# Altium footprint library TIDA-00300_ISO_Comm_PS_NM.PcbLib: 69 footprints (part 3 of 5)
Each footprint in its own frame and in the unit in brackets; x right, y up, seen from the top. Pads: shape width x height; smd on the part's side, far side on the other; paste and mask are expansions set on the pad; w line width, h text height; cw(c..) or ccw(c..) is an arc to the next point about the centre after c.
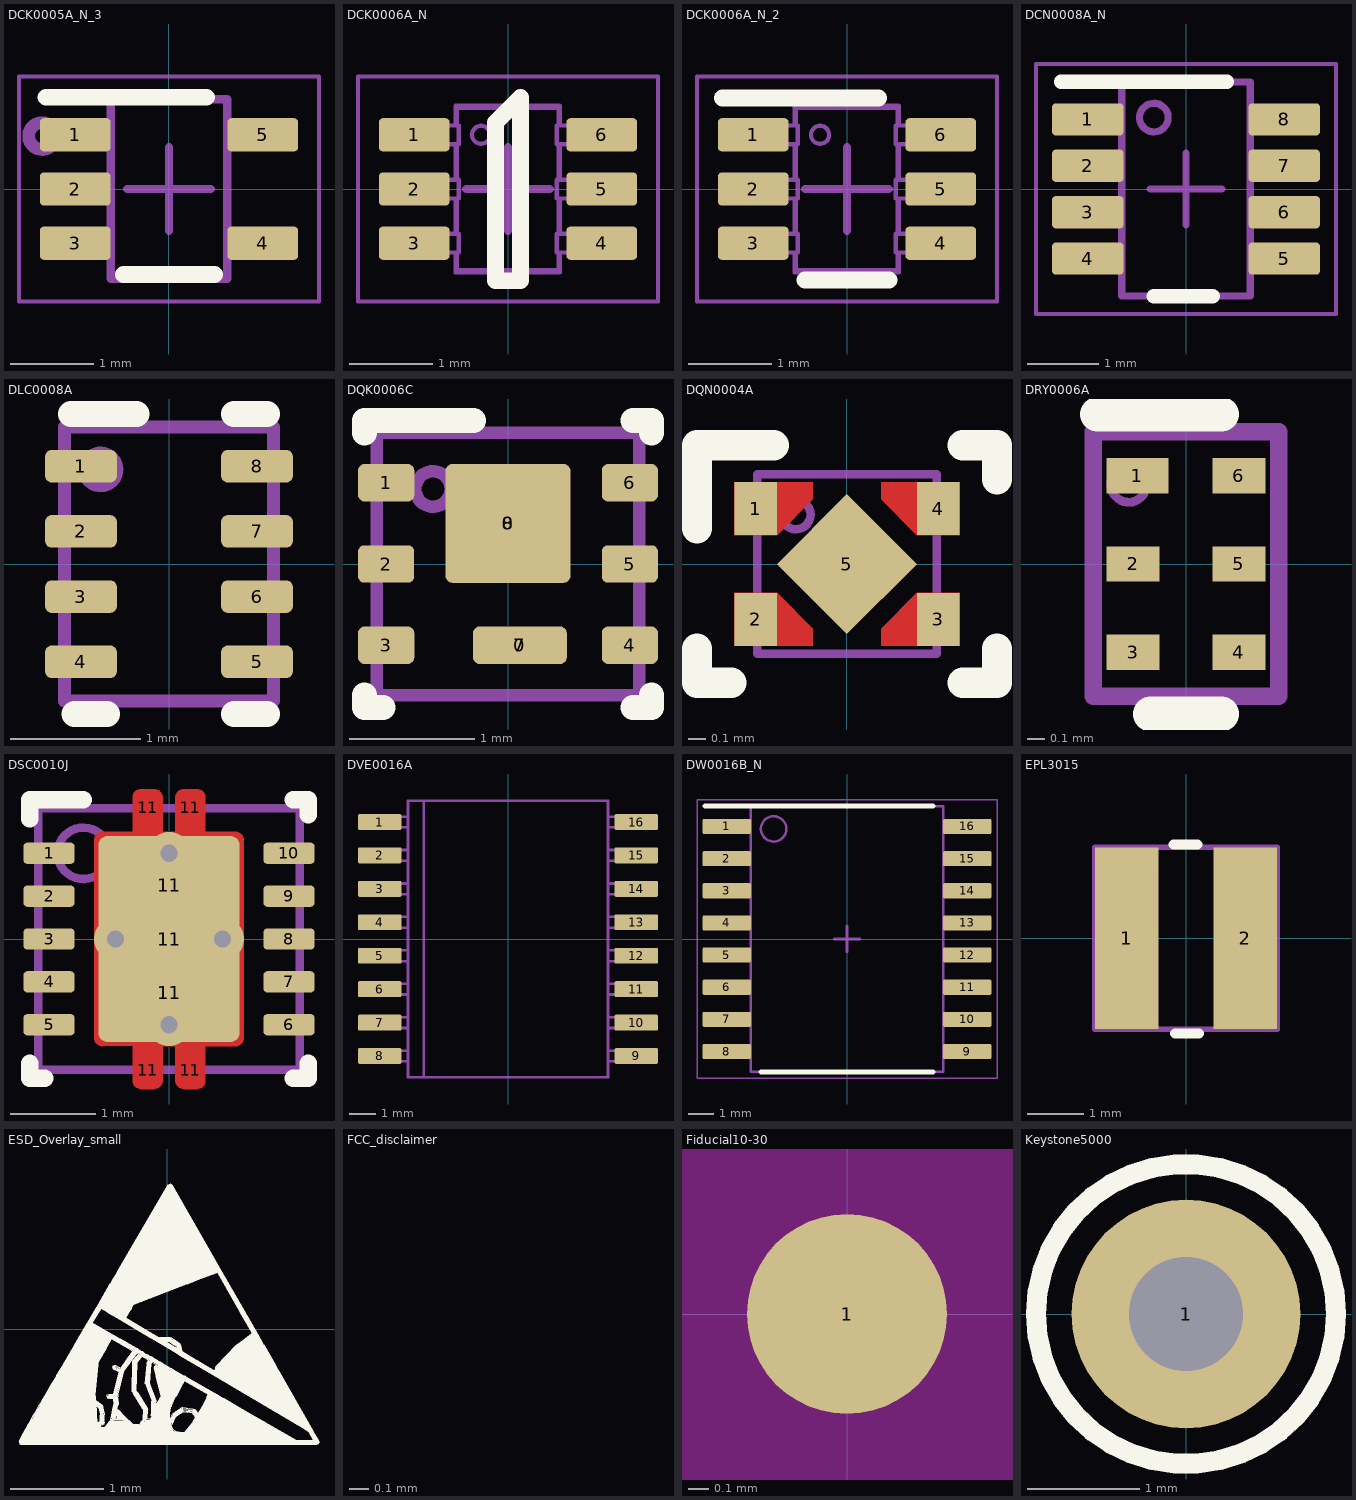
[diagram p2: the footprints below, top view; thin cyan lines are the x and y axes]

## DCK0005A_N_3 [mm]
pads (5):
  rrect25% 0.85x0.4 smd: 1(-1.125,0.65) 2(-1.125,0) 3(-1.125,-0.65) 4(1.125,-0.65) 5(1.125,0.65)
Top Overlay:
  lines w0.2: -1.475,1.1 0.45,1.1 ; -0.55,-1.025 0.55,-1.025
Mechanical 5:
  circle w0.152: c-1.524,0.635 r0.16
  lines w0.1: -0.7,-1.075 0.7,-1.075 0.7,1.075 -0.7,1.075 -0.7,-1.075
  lines w0.127: -0.865,0.762 -0.853,0.762 ; -0.711,-0.763 -0.853,-0.763 -0.865,-0.763 -0.959,-0.763 -1.143,-0.763 -1.143,-0.538 -0.959,-0.538 -0.865,-0.538 -0.853,-0.538 -0.711,-0.538 ; -0.711,-0.113 -0.853,-0.113 -0.865,-0.113 -0.959,-0.113 -1.143,-0.113 -1.143,0.112 -0.959,0.112 -0.865,0.112 -0.853,0.112 -0.711,0.112 ; -0.711,0.537 -0.853,0.537 -0.865,0.537 -0.959,0.537 -1.143,0.537 -1.143,0.762 -0.959,0.762 -0.711,0.762 ; 0.711,-0.763 0.847,-0.763 0.859,-0.763 0.953,-0.763 1.137,-0.763 1.137,-0.538 0.953,-0.538 0.859,-0.538 0.847,-0.538 0.711,-0.538 ; 0.711,0.537 0.847,0.537 0.859,0.537 0.953,0.537 1.137,0.537 1.137,0.762 0.953,0.762 0.859,0.762 0.847,0.762 0.711,0.762
  text ".Designator" at -0.254,0.537 h0.51
Mechanical 15:
  lines w0.05: -1.8,-1.35 1.8,-1.35 1.8,1.35 -1.8,1.35 -1.8,-1.35
  lines w0.1: -0.5,0 0.5,0 ; 0,-0.5 0,0.5
3D body "DCK0005A.stp": height 0.95, standoff 0, extent -1.14,-1 1.14,1

## DCK0006A_N [mm] "SOT23, 6-Leads, Body 2x1.3mm, Pitch 0.65mm, Lead Span 2.1mm, IPC Medium Density"
height 1.1
pads (6):
  rrect25% 0.85x0.4 smd: 1(-1.125,0.65) 2(-1.125,0) 3(-1.125,-0.65) 4(1.125,-0.65) 5(1.125,0) 6(1.125,0.65)
Top Overlay:
  lines w0.2: -0.15,-1.1 0.15,-1.1 0.15,1.1 -0.15,0.8 -0.15,-1.1
Mechanical 5:
  lines w0.05: -0.613,-0.763 -0.613,-0.976 0.607,-0.976 0.607,-0.763 ; -0.613,-0.538 -0.613,-0.113 ; -0.613,0.112 -0.613,0.537 ; -0.613,0.762 -0.613,0.974 0.607,0.974 0.607,0.762 ; 0.607,-0.538 0.607,-0.113 ; 0.607,0.112 0.607,0.537 ; -0.628,-0.763 -0.591,-0.763 -0.591,-0.538 -0.628,-0.538 ; -0.628,-0.763 -0.853,-0.763 -0.865,-0.763 -0.959,-0.763 -1.143,-0.763 -1.143,-0.538 -0.959,-0.538 -0.865,-0.538 -0.853,-0.538 -0.628,-0.538 ; -0.628,-0.763 -0.628,-1.001 0.622,-1.001 0.622,-0.763 ; -0.628,-0.538 -0.628,-0.113 ; -0.628,-0.113 -0.591,-0.113 -0.591,0.112 -0.628,0.112 ; -0.628,-0.113 -0.853,-0.113 -0.865,-0.113 -0.959,-0.113 -1.143,-0.113 -1.143,0.112 -0.959,0.112 -0.865,0.112 -0.853,0.112 -0.628,0.112 ; -0.628,0.112 -0.628,0.537 ; -0.628,0.537 -0.591,0.537 -0.591,0.762 -0.628,0.762 ; -0.628,0.537 -0.853,0.537 -0.865,0.537 -0.959,0.537 -1.143,0.537 -1.143,0.762 -0.959,0.762 -0.865,0.762 -0.853,0.762 -0.628,0.762 ; -0.628,0.762 -0.628,0.999 0.622,0.999 0.622,0.762 ; 0.622,-0.763 0.585,-0.763 0.585,-0.538 0.622,-0.538 ; 0.622,-0.763 0.847,-0.763 0.859,-0.763 0.953,-0.763 1.137,-0.763 1.137,-0.538 0.953,-0.538 0.859,-0.538 0.847,-0.538 0.622,-0.538 ; 0.622,-0.538 0.622,-0.113 ; 0.622,-0.113 0.847,-0.113 0.859,-0.113 0.953,-0.113 1.137,-0.113 1.137,0.112 0.953,0.112 0.859,0.112 0.847,0.112 0.622,0.112 ; 0.622,-0.113 0.585,-0.113 0.585,0.112 0.622,0.112 ; 0.622,0.112 0.622,0.537 ; 0.622,0.537 0.585,0.537 0.585,0.762 0.622,0.762 ; 0.622,0.537 0.847,0.537 0.859,0.537 0.953,0.537 1.137,0.537 1.137,0.762 0.953,0.762 0.859,0.762 0.847,0.762 0.622,0.762 ; -0.432,0.65 ccw(c-0.323,0.65) -0.215,0.65 ccw(c-0.323,0.65) -0.432,0.65
  text ".Designator" at 0.279,-0.635 h0.51
Mechanical 15:
  lines w0.05: -1.8,-1.35 1.8,-1.35 1.8,1.35 -1.8,1.35 -1.8,-1.35
  lines w0.1: -0.5,0 0.5,0 ; 0,-0.5 0,0.5
3D body "DCK0006A.stp": height 0.95, standoff 0, extent -1.14,-1 1.14,1

## DCK0006A_N_2 [mm]
pads (6):
  rrect25% 0.85x0.4 smd: 1(-1.125,0.65) 2(-1.125,0) 3(-1.125,-0.65) 4(1.125,-0.65) 5(1.125,0) 6(1.125,0.65)
Top Overlay:
  lines w0.2: -1.499,1.092 0.381,1.092 ; -0.508,-1.092 0.508,-1.092
Mechanical 5:
  lines w0.05: -0.613,-0.763 -0.613,-0.976 0.607,-0.976 0.607,-0.763 ; -0.613,-0.538 -0.613,-0.113 ; -0.613,0.112 -0.613,0.537 ; -0.613,0.762 -0.613,0.974 0.607,0.974 0.607,0.762 ; 0.607,-0.538 0.607,-0.113 ; 0.607,0.112 0.607,0.537 ; -0.628,-0.763 -0.591,-0.763 -0.591,-0.538 -0.628,-0.538 ; -0.628,-0.763 -0.853,-0.763 -0.865,-0.763 -0.959,-0.763 -1.143,-0.763 -1.143,-0.538 -0.959,-0.538 -0.865,-0.538 -0.853,-0.538 -0.628,-0.538 ; -0.628,-0.763 -0.628,-1.001 0.622,-1.001 0.622,-0.763 ; -0.628,-0.538 -0.628,-0.113 ; -0.628,-0.113 -0.591,-0.113 -0.591,0.112 -0.628,0.112 ; -0.628,-0.113 -0.853,-0.113 -0.865,-0.113 -0.959,-0.113 -1.143,-0.113 -1.143,0.112 -0.959,0.112 -0.865,0.112 -0.853,0.112 -0.628,0.112 ; -0.628,0.112 -0.628,0.537 ; -0.628,0.537 -0.591,0.537 -0.591,0.762 -0.628,0.762 ; -0.628,0.537 -0.853,0.537 -0.865,0.537 -0.959,0.537 -1.143,0.537 -1.143,0.762 -0.959,0.762 -0.865,0.762 -0.853,0.762 -0.628,0.762 ; -0.628,0.762 -0.628,0.999 0.622,0.999 0.622,0.762 ; 0.622,-0.763 0.585,-0.763 0.585,-0.538 0.622,-0.538 ; 0.622,-0.763 0.847,-0.763 0.859,-0.763 0.953,-0.763 1.137,-0.763 1.137,-0.538 0.953,-0.538 0.859,-0.538 0.847,-0.538 0.622,-0.538 ; 0.622,-0.538 0.622,-0.113 ; 0.622,-0.113 0.847,-0.113 0.859,-0.113 0.953,-0.113 1.137,-0.113 1.137,0.112 0.953,0.112 0.859,0.112 0.847,0.112 0.622,0.112 ; 0.622,-0.113 0.585,-0.113 0.585,0.112 0.622,0.112 ; 0.622,0.112 0.622,0.537 ; 0.622,0.537 0.585,0.537 0.585,0.762 0.622,0.762 ; 0.622,0.537 0.847,0.537 0.859,0.537 0.953,0.537 1.137,0.537 1.137,0.762 0.953,0.762 0.859,0.762 0.847,0.762 0.622,0.762 ; -0.432,0.65 ccw(c-0.323,0.65) -0.215,0.65 ccw(c-0.323,0.65) -0.432,0.65
  text ".Designator" at -0.152,0.381 h0.51
Mechanical 15:
  lines w0.05: -1.8,-1.35 1.8,-1.35 1.8,1.35 -1.8,1.35 -1.8,-1.35
  lines w0.1: -0.5,0 0.5,0 ; 0,-0.5 0,0.5
3D body "DCK0006A.stp": height 0.95, standoff 0, extent -1.14,-1 1.14,1

## DCN0008A_N [mm] "SOP, 8-Leads, Body 2.9x1.6mm, Pitch 0.65mm, IPC Medium Density"
height 1.45
pads (8):
  rrect22% 1x0.45 smd: 1(-1.375,0.975) 2(-1.375,0.325) 3(-1.375,-0.325) 4(-1.375,-0.975) 5(1.375,-0.975) 6(1.375,-0.325) 7(1.375,0.325) 8(1.375,0.975)
Top Overlay:
  lines w0.2: -1.75,1.5 0.575,1.5 ; -0.45,-1.5 0.375,-1.5
Mechanical 5:
  circle w0.1: c-0.45,1 r0.2
  lines w0.1: -0.9,-1.5 -0.9,1.5 0.9,1.5 0.9,-1.5 -0.9,-1.5
  text ".Designator" at -0.66,-0.503 h0.51
Mechanical 15:
  lines w0.05: -2.1,-1.75 2.1,-1.75 2.1,1.75 -2.1,1.75 -2.1,-1.75
  lines w0.1: -0.5,0 0.5,0 ; 0,-0.5 0,0.5
3D body "DCN0008A.stp": height 1.45, standoff 0, extent -1.405,-1.45 1.405,1.45

## DLC0008A [mm] "VSON-HR-8"
height 1
pads (8):
  rrect40% 0.55x0.25 smd: 1(-0.675,0.75) 2(-0.675,0.25) 3(-0.675,-0.25) 4(-0.675,-0.75) 5(0.675,-0.75) 6(0.675,-0.25) 7(0.675,0.25) 8(0.675,0.75)
Top Overlay:
  lines w0.2: -0.75,1.15 -0.25,1.15 ; -0.725,-1.15 -0.475,-1.15 ; 0.5,-1.15 0.75,-1.15 ; 0.5,1.15 0.75,1.15
Mechanical 5:
  circle w0.1: c-0.525,0.725 r0.125
  lines w0.1: -0.8,-1.05 -0.8,1.05 0.8,1.05 0.8,-1.05 -0.8,-1.05
  text ".Designator" at -0.265,2.579 h0.51
3D body: height 1, standoff 0, extent -0.799,-1.049 0.799,1.049
3D body: height 1.02, standoff 0.5, extent -0.549,0.601 -0.301,0.849

## DQK0006C [mm] "WSON"
height 0.8
pads (10):
  rrect50% 0.9x0.86 on Top Paste: 0(0,0.325)
  rrect50% 0.7x0.29 on Top Paste: 0(0.095,-0.65)
  rrect33% 0.45x0.3 smd: 1(-0.975,0.65) 2(-0.975,0) 3(-0.975,-0.65) 4(0.975,-0.65) 5(0.975,0) 6(0.975,0.65)
  rrect33% 0.75x0.3 smd paste-0.15: 7(0.095,-0.65)
  rrect11% 1x0.95 smd paste-0.5: 8(0,0.325)
Top Overlay:
  lines w0.2: -1.15,-1.05 -1.15,-1.15 -1,-1.15 ; -1.15,1.05 -1.15,1.15 -0.275,1.15 ; 1,-1.15 1.15,-1.15 1.15,-1.05 ; 1,1.15 1.15,1.15 1.15,1.05
Mechanical 5:
  circle w0.1: c-0.6,0.6 r0.141
  lines w0.1: -1.05,-1.05 -1.05,1.05 1.05,1.05 1.05,-1.05 -1.05,-1.05
  text ".Designator" at 0.193,0.163 h0.51
3D body "DQK0006C.stp": height 0.82, standoff 0, extent -1,-1 1,1

## DQN0004A [mm] "SON, 0.65mm pitch"
height 0.4
pads (5):
  rect 0.25x0.31 smd paste-1 mask-0.31: 1(-0.535,0.325) 2(-0.535,-0.325) 3(0.535,-0.325) 4(0.535,0.325)
  rect 0.58x0.58 smd rot 45 paste-0.065 mask-0.05: 5(0,0)
Top Layer:
  region: -0.66,0.48 -0.2,0.48 -0.2,0.379 -0.409,0.17 -0.66,0.17
  region: 0.66,0.48 0.2,0.48 0.2,0.379 0.409,0.17 0.66,0.17
  region: 0.66,-0.48 0.2,-0.48 0.2,-0.379 0.409,-0.17 0.66,-0.17
  region: -0.66,-0.48 -0.2,-0.48 -0.2,-0.379 -0.409,-0.17 -0.66,-0.17
Top Overlay:
  lines w0.178: -0.88,-0.496 -0.88,-0.696 -0.68,-0.696 ; -0.88,0.21 -0.88,0.696 -0.43,0.696 ; 0.68,-0.696 0.88,-0.696 0.88,-0.496 ; 0.68,0.696 0.88,0.696 0.88,0.496
Top Paste:
  region: -0.65,-0.43 -0.25,-0.43 -0.25,-0.4 -0.43,-0.22 -0.65,-0.22
  region: 0.65,-0.43 0.25,-0.43 0.25,-0.4 0.43,-0.22 0.65,-0.22
  region: 0.65,0.43 0.25,0.43 0.25,0.4 0.43,0.22 0.65,0.22
  region: -0.65,0.43 -0.25,0.43 -0.25,0.4 -0.43,0.22 -0.65,0.22
Mechanical 5:
  circle w0.05: c-0.3,0.29 r0.086
  lines w0.05: -0.525,-0.525 -0.525,0.525 0.525,0.525 0.525,-0.525 -0.525,-0.525
  text ".Designator" at 0.616,-0.781 h0.51
3D body: height 0.4, standoff 0, extent -0.525,-0.525 0.525,0.525
3D body: height 0.42, standoff 0.2, extent -0.386,0.204 -0.214,0.376

## DRY0006A [mm] "PSON, 6-Leads, Body 1x1.45mm, Pitch 0.5mm, TI Recommended"
height 0.6
pads (6):
  rect 0.35x0.2 smd: 1(-0.275,0.5)
  rect 0.3x0.2 smd: 2(-0.3,0) 3(-0.3,-0.5) 4(0.3,-0.5) 5(0.3,0) 6(0.3,0.5)
Top Overlay:
  lines w0.2: -0.5,0.85 0.2,0.85 ; -0.2,-0.85 0.2,-0.85
Mechanical 5:
  circle w0.05: c-0.325,0.45 r0.1
  lines w0.1: -0.525,-0.75 -0.525,0.75 0.525,0.75 0.525,-0.75 -0.525,-0.75
  text ".Designator" at 0.517,1.552 h0.51
3D body: height 0.6, standoff 0, extent -0.525,-0.75 0.525,0.75
3D body: height 0.61, standoff 0.3, extent -0.424,0.351 -0.226,0.549

## DSC0010J [mm] "SON, 10-Leads, Body 3x3mm, Pitch 0.5mm, Thermal Pad 2.4x1.65mm, TI Recommended"
height 0.8
pads (17):
  rrect40% 0.6x0.25 smd: 1(-1.4,1) 2(-1.4,0.5) 3(-1.4,0) 4(-1.4,-0.5) 5(-1.4,-1) 6(1.4,-1) 7(1.4,-0.5) 8(1.4,0) 9(1.4,0.5) 10(1.4,1)
  rrect50% 0.25x0.34 on Top Paste: 11(-0.25,-1.53) 11(-0.25,1.53) 11(0.25,-1.53) 11(0.25,1.53)
  rrect50% 1.5x1.06 on Top Paste: 11(0,-0.63) 11(0,0.63)
  rrect12% 1.65x2.4 smd paste-1 mask-2: 11(0,0)
via 0.625,0 diameter 0.5 hole 0.2
via -0.625,0 diameter 0.5 hole 0.2
via 0,1 diameter 0.5 hole 0.2
via 0,-1 diameter 0.5 hole 0.2
Top Layer:
  region: -0.775,-1.25 -0.425,-1.25 -0.425,-1.65 -0.425,-1.67 -0.41,-1.707 -0.382,-1.735 -0.345,-1.75 -0.325,-1.75 -0.175,-1.75 -0.155,-1.75 -0.118,-1.735 -0.09,-1.707 -0.075,-1.67 -0.075,-1.65 -0.075,-1.25 0.075,-1.25 0.075,-1.65 0.075,-1.67 0.09,-1.707 0.118,-1.735 0.155,-1.75 0.175,-1.75 0.325,-1.75 0.345,-1.75 0.382,-1.735 0.41,-1.707 0.425,-1.67 0.425,-1.65 0.425,-1.25 0.775,-1.25 0.795,-1.25 0.832,-1.235 0.86,-1.207 0.875,-1.17 0.875,-1.15 0.875,1.15 0.875,1.17 0.86,1.207 0.832,1.235 0.795,1.25 0.775,1.25 0.425,1.25 0.425,1.65 0.425,1.67 0.41,1.707 0.382,1.735 0.345,1.75 0.325,1.75 0.175,1.75 0.155,1.75 0.118,1.735 0.09,1.707 0.075,1.67 0.075,1.65 0.075,1.25 -0.075,1.25 -0.075,1.65 -0.075,1.67 -0.09,1.707 -0.118,1.735 -0.155,1.75 -0.175,1.75 -0.325,1.75 -0.345,1.75 -0.382,1.735 -0.41,1.707 -0.425,1.67 -0.425,1.65 -0.425,1.25 -0.775,1.25 -0.795,1.25 -0.832,1.235 -0.86,1.207 -0.875,1.17 -0.875,1.15 -0.875,-1.15 -0.875,-1.17 -0.86,-1.207 -0.832,-1.235 -0.795,-1.25
Top Overlay:
  lines w0.2: -1.625,-1.45 -1.625,-1.625 -1.45,-1.625 ; -1.625,1.4 -1.625,1.625 -1,1.625 ; 1.45,-1.625 1.625,-1.625 1.625,-1.45 ; 1.45,1.625 1.625,1.625 1.625,1.45
Mechanical 5:
  circle w0.1: c-1,1 r0.3
  lines w0.1: -1.525,-1.525 1.525,-1.525 1.525,1.525 -1.525,1.525 -1.525,-1.525
  text ".Designator" at -4.031,-1.702 h0.51
3D body "DSC0010J.stp": height 0.81, standoff 0.01, extent -1.5,-1.5 1.5,1.5

## DVE0016A [mm] "SO-MOD-16"
height 2.65
pads (16):
  rrect17% 1.65x0.6 smd: 1(-4.875,4.445) 2(-4.875,3.175) 3(-4.875,1.905) 4(-4.875,0.635) 5(-4.875,-0.635) 6(-4.875,-1.905) 7(-4.875,-3.175) 8(-4.875,-4.445) 9(4.875,-4.445) 10(4.875,-3.175) 11(4.875,-1.905) 12(4.875,-0.635) 13(4.875,0.635) 14(4.875,1.905) 15(4.875,3.175) 16(4.875,4.445)
Mechanical 5:
  lines w0.1: -3.8,-4.65 -5.3,-4.65 -5.3,-4.24 -3.8,-4.24 ; -3.8,-3.38 -5.3,-3.38 -5.3,-2.97 -3.8,-2.97 ; -3.8,-2.11 -5.3,-2.11 -5.3,-1.7 -3.8,-1.7 ; -3.8,-0.84 -5.3,-0.84 -5.3,-0.43 -3.8,-0.43 ; -3.8,0.43 -5.3,0.43 -5.3,0.84 -3.8,0.84 ; -3.8,1.7 -5.3,1.7 -5.3,2.11 -3.8,2.11 ; -3.8,2.97 -5.3,2.97 -5.3,3.38 -3.8,3.38 ; -3.8,4.24 -5.3,4.24 -5.3,4.65 -3.8,4.65 ; -3.2,-5.25 -3.2,5.25 ; 3.8,-4.65 5.3,-4.65 5.3,-4.24 3.8,-4.24 ; 3.8,-3.38 5.3,-3.38 5.3,-2.97 3.8,-2.97 ; 3.8,-2.11 5.3,-2.11 5.3,-1.7 3.8,-1.7 ; 3.8,-0.84 5.3,-0.84 5.3,-0.43 3.8,-0.43 ; 3.8,0.43 5.3,0.43 5.3,0.84 3.8,0.84 ; 3.8,1.7 5.3,1.7 5.3,2.11 3.8,2.11 ; 3.8,2.97 5.3,2.97 5.3,3.38 3.8,3.38 ; 3.8,4.24 5.3,4.24 5.3,4.65 3.8,4.65 ; -3.8,-5.25 3.8,-5.25 3.8,5.25 -3.8,5.25 -3.8,-5.25
  text ".Designator" at -5.869,-0.787 h0.51
3D body "DVE0016A.stp": height 2.59, standoff 0, extent -5.167,-5.15 5.168,5.15

## DW0016B_N [mm] "SOIC, 16-Leads, Body 10.5x7.6mm, Pitch 1.27mm, IPC Medium Density"
height 2.65
pads (16):
  rrect17% 1.9x0.6 smd: 1(-4.75,4.445) 2(-4.75,3.175) 3(-4.75,1.905) 4(-4.75,0.635) 5(-4.75,-0.635) 6(-4.75,-1.905) 7(-4.75,-3.175) 8(-4.75,-4.445) 9(4.75,-4.445) 10(4.75,-3.175) 11(4.75,-1.905) 12(4.75,-0.635) 13(4.75,0.635) 14(4.75,1.905) 15(4.75,3.175) 16(4.75,4.445)
Top Overlay:
  lines w0.2: -5.6,5.25 3.4,5.25 ; -3.4,-5.25 3.4,-5.25
Mechanical 5:
  circle w0.1: c-2.9,4.35 r0.5
  lines w0.1: -3.8,-5.25 3.8,-5.25 3.8,5.25 -3.8,5.25 -3.8,-5.25
  text ".Designator" at -0.584,0.178 h0.51
Mechanical 13:
  circle w0.1: c-2.9,4.35 r0.5
  lines w0.1: -3.8,-5.25 -3.8,5.25 3.8,5.25 3.8,-5.25 -3.8,-5.25
Mechanical 15:
  lines w0.05: -5.925,-5.5 -5.925,5.5 5.925,5.5 5.925,-5.5 -5.925,-5.5
  lines w0.1: -0.5,0 0.5,0 ; 0,-0.5 0,0.5
3D body "DW0016B.stp": height 2.59, standoff 0, extent -5.167,-5.15 5.167,5.15

## EPL3015 [mm] "COILCRAFT"
height 1.55
pads (2):
  rect 1.12x3.2 smd: 1(-1.04,0) 2(1.04,0)
Top Overlay:
  lines w0.178: -0.22,1.65 0.2,1.65 ; -0.195,-1.675 0.225,-1.675
Mechanical 5:
  lines w0.1: -1.6,-1.6 1.6,-1.6 1.6,1.6 -1.6,1.6 -1.6,-1.6
  text ".Designator" at 0.254,-0.381 h0.51
3D body: height 1.55, standoff 0, extent -1.599,-1.599 1.599,1.599

## ESD_Overlay_small [mm]
height 1.45
Top Overlay:
  drawing of 901 lines, arcs and shapes, not listed

## FCC_disclaimer [mm]
Top Overlay:
  text "For evaluation only; not FCC approved for resale." at -15.572,-12.418 h1.52

## Fiducial10-30 [mm]
height 7.6
pads (1):
  round 1 smd mask+1: 1(0,0)
Top Layer keep-out:
  circle w1.678: c0,0 r0.75

## Keystone5000 [mil] "For Keystone 500x miniature loop terminals"
height 181.1
pads (1):
  round 80 hole 40: 1(0,0)
Top Overlay:
  circle w7: c0,0 r52.5
Mechanical 5:
  circle w3.94: c0,0 r52.5
  text ".Designator" at 70,-107 h20
3D body "Keystone_5000.stp": height 181.97, standoff -118.11, extent -49,-49 49.04,49.24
